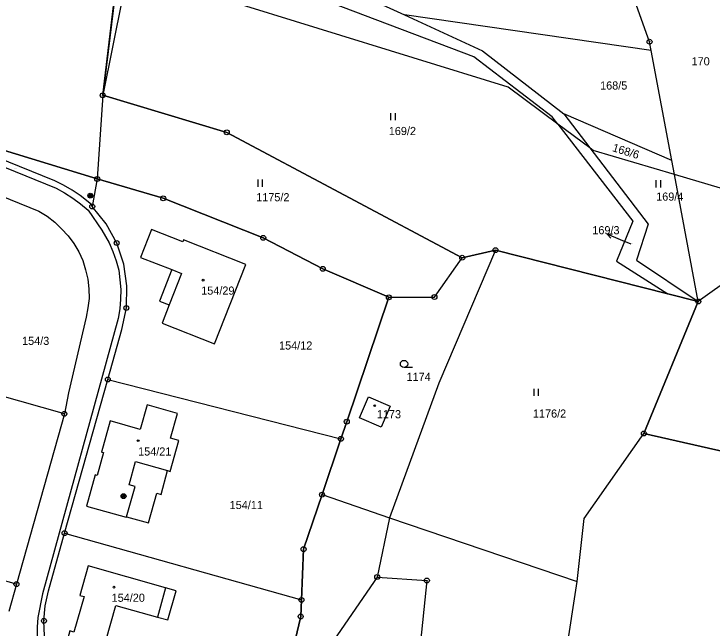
# Model space of a CAD drawing. Extents: x -737240 to -735272, y -1119606 to -1117878.
# Drawn here: x -736684.5 to -736538.4, y -1119343.1 to -1119214.7 of the extents above; entities that cross this region are included whole.
import ezdxf

# ---------------------------------------------------------------- set-up
doc = ezdxf.new("R2010")
doc.units = 0
for name, color, linetype in [('Level 1', 7, 'Continuous'), ('Level 13', 7, 'Continuous'), ('Level 16', 7, 'Continuous'), ('Level 18', 7, 'Continuous'), ('Level 19', 7, 'Continuous'), ('Level 25', 7, 'Continuous'), ('Level 4', 7, 'Continuous')]:
    doc.layers.add(name, color=color, linetype=linetype)

msp = doc.modelspace()

# ---------------------------------------------------------------- linework, layer by layer
at = {"layer": 'Level 1'}
for p, q in [((-736665.92, -1119231.67), (-736662.64, -1119204.74)), ((-736660.57, -1119205.38), (-736665.92, -1119231.67)), ((-736551.17, -1119222.28), (-736602.8, -1119214.86)), ((-736546.85, -1119245.3), (-736551.17, -1119222.28)), ((-736665.92, -1119231.67), (-736667.06, -1119249.16)), ((-736569.47, -1119235.51), (-736564, -1119242.68)), ((-736546.85, -1119245.3), (-736569.47, -1119235.51)), ((-736564, -1119242.68), (-736570.67, -1119237.72)), ((-736546.3, -1119248.23), (-736546.85, -1119245.3)), ((-736667.06, -1119249.16), (-736668.11, -1119254.91)), ((-736541.31, -1119274.79), (-736546.3, -1119248.23)), ((-736536.7, -1119251.07), (-736546.3, -1119248.23)), ((-736590.7, -1119265.63), (-736583.76, -1119264.06)), ((-736541.31, -1119274.79), (-736547.66, -1119273.19)), ((-736673.94, -1119298.28), (-736743.14, -1119278.79)), ((-736673.89, -1119323.23), (-736664.84, -1119291.08)), ((-736664.84, -1119291.08), (-736616.08, -1119303.51)), ((-736673.94, -1119298.28), (-736683.96, -1119333.89)), ((-736620.03, -1119315.17), (-736605.9, -1119319.98)), ((-736605.9, -1119319.98), (-736608.48, -1119332.39)), ((-736605.9, -1119319.98), (-736566.63, -1119333.35)), ((-736683.96, -1119333.89), (-736726.33, -1119321.96)), ((-736673.89, -1119323.23), (-736624.34, -1119337.18)), ((-736683.96, -1119333.89), (-736685.57, -1119339.6))]:
    msp.add_line(p, q, dxfattribs=at)
for points in [[(-736667.06, -1119249.16), (-736691.06, -1119241.83), (-736704.74, -1119235.5), (-736723.73, -1119226.81), (-736743.15, -1119221.74), (-736738.77, -1119203.51), (-736735.65, -1119190.52), (-736731.56, -1119173.9), (-736724.99, -1119172.93), (-736717.53, -1119171.82), (-736710.06, -1119170.71), (-736704.98, -1119169.96), (-736702.42, -1119170.42), (-736693.71, -1119172), (-736673.69, -1119175.61), (-736662.64, -1119204.74), (-736665.92, -1119231.67)], [(-736667.36, -1119176.68), (-736655.78, -1119192.66), (-736619.36, -1119207.27), (-736602.8, -1119214.86)], [(-736551.17, -1119222.28), (-736551.51, -1119220.47), (-736560.76, -1119194.73)], [(-736570.67, -1119237.72), (-736571.87, -1119236.16), (-736588.24, -1119223.64), (-736658.83, -1119196.84)], [(-736570.67, -1119237.72), (-736581.11, -1119229.95), (-736660.57, -1119205.38)], [(-736668.11, -1119254.91), (-736668.26, -1119254.47), (-736670.65, -1119252.61), (-736672.34, -1119251.49), (-736674.09, -1119250.44), (-736675.92, -1119249.53), (-736724.83, -1119229.75), (-736740.44, -1119225.23), (-736766.11, -1119219.16), (-736789.8, -1119214.25), (-736792.59, -1119213.62), (-736794.57, -1119213.03), (-736796.41, -1119212.17), (-736798.16, -1119211.14), (-736800.29, -1119209.7), (-736802.05, -1119208.36)], [(-736602.8, -1119214.86), (-736586.47, -1119222.35), (-736569.47, -1119235.51)], [(-736743.15, -1119221.74), (-736723.73, -1119226.81), (-736704.74, -1119235.5), (-736691.06, -1119241.83), (-736667.06, -1119249.16)], [(-736725.28, -1119230.97), (-736675.67, -1119251.11), (-736673.88, -1119252.07), (-736672.17, -1119253.15), (-736670.53, -1119254.37), (-736668.98, -1119255.66), (-736666.07, -1119259.85), (-736664.6, -1119262.5), (-736663.8, -1119264.36), (-736663.12, -1119266.27), (-736662.56, -1119268.23), (-736662.12, -1119272.27), (-736662.17, -1119274.3), (-736662.34, -1119276.33), (-736662.7, -1119278.32), (-736678.5, -1119335.91), (-736679.46, -1119340.86), (-736679.62, -1119342.87), (-736679.66, -1119344.9)], [(-736665.92, -1119231.67), (-736639.96, -1119239.42), (-736590.7, -1119265.63)], [(-736547.66, -1119273.19), (-736583.76, -1119264.06), (-736590.7, -1119265.63), (-736639.96, -1119239.42), (-736665.92, -1119231.67)], [(-736727.41, -1119236.65), (-736721.33, -1119238.79), (-736679.28, -1119255.92), (-736677.56, -1119256.95), (-736675.95, -1119258.17), (-736674.51, -1119259.56), (-736673.16, -1119261.07), (-736671.93, -1119262.67), (-736670.89, -1119264.4), (-736670.07, -1119266.22), (-736669.49, -1119268.16), (-736669.01, -1119270.12), (-736668.79, -1119272.11), (-736668.75, -1119274.14), (-736669.01, -1119276.12), (-736669.38, -1119278.07), (-736673.08, -1119293.85), (-736673.94, -1119298.28)], [(-736570.67, -1119237.72), (-736555.03, -1119257.98), (-736558.4, -1119266.33), (-736547.66, -1119273.19)], [(-736564, -1119242.68), (-736551.82, -1119258.62), (-736554.23, -1119266.17), (-736541.31, -1119274.79)], [(-736546.3, -1119248.23), (-736563.32, -1119243.18), (-736564, -1119242.68)], [(-736606.04, -1119273.9), (-736619.86, -1119267.96), (-736632.34, -1119261.47), (-736653.26, -1119253.2), (-736667.06, -1119249.16)], [(-736667.06, -1119249.16), (-736653.26, -1119253.2), (-736632.34, -1119261.47), (-736619.86, -1119267.96), (-736606.04, -1119273.9), (-736614.86, -1119299.91), (-736616.08, -1119303.51)], [(-736664.84, -1119291.08), (-736661.91, -1119280.67), (-736660.97, -1119276.14), (-736660.84, -1119271.52), (-736661.52, -1119266.95), (-736662.99, -1119262.56), (-736665.21, -1119258.51), (-736668.11, -1119254.91)], [(-736652.01, -1119275.5), (-736653.51, -1119279.28), (-736642.5, -1119283.65), (-736635.96, -1119267.07), (-736649.01, -1119261.87), (-736649.18, -1119262.29), (-736655.68, -1119259.72), (-736657.98, -1119265.55), (-736651.46, -1119268.12)], [(-736583.76, -1119264.06), (-736595.59, -1119291.89), (-736605.9, -1119319.98)], [(-736583.76, -1119264.06), (-736547.66, -1119273.19), (-736541.31, -1119274.79), (-736552.7, -1119302.39)], [(-736514.13, -1119266.89), (-736526.79, -1119264.4), (-736541.31, -1119274.79)], [(-736606.04, -1119273.9), (-736596.5, -1119273.85), (-736590.7, -1119265.63)], [(-736651.46, -1119268.12), (-736654.03, -1119274.69), (-736652.01, -1119275.5)], [(-736552.7, -1119302.39), (-736528.73, -1119307.83), (-736514.13, -1119266.89), (-736506.87, -1119269.54)], [(-736514.13, -1119266.89), (-736528.73, -1119307.83), (-736552.7, -1119302.39), (-736541.31, -1119274.79)], [(-736620.03, -1119315.17), (-736616.08, -1119303.51), (-736614.86, -1119299.91), (-736606.04, -1119273.9)], [(-736607.63, -1119301.03), (-736612.17, -1119299.1), (-736610.34, -1119294.74), (-736605.78, -1119296.68), (-736607.63, -1119301.03)], [(-736652.33, -1119310.15), (-736651.82, -1119310.3), (-736649.98, -1119303.84), (-736651.71, -1119303.34), (-736650.26, -1119298.23), (-736656.62, -1119296.42), (-736658.07, -1119301.52), (-736664.33, -1119299.74), (-736666.16, -1119306.26), (-736665.74, -1119306.37), (-736667.08, -1119311.17), (-736667.5, -1119311.05), (-736669.33, -1119317.54), (-736660.99, -1119319.86), (-736660.96, -1119319.78)], [(-736566.63, -1119333.35), (-736565.21, -1119320.17), (-736552.7, -1119302.39)], [(-736616.08, -1119303.51), (-736620.03, -1119315.17), (-736623.89, -1119326.56), (-736624.34, -1119337.18)], [(-736660.96, -1119319.78), (-736656.35, -1119321.09), (-736654.58, -1119314.89), (-736653.71, -1119315.14), (-736652.33, -1119310.15)], [(-736631.83, -1119443.36), (-736631.2, -1119439.41), (-736629.41, -1119428.11), (-736626.1, -1119402.13), (-736624.78, -1119391.75), (-736629.05, -1119368.06), (-736629.89, -1119363.38), (-736624.49, -1119340.65), (-736624.34, -1119337.18), (-736623.89, -1119326.56), (-736620.03, -1119315.17)], [(-736675.06, -1119355.1), (-736675.62, -1119353.87), (-736676.81, -1119350.93), (-736677.65, -1119347.86), (-736678.12, -1119344.72), (-736678.21, -1119341.54), (-736677.94, -1119338.4), (-736677.28, -1119335.26), (-736673.89, -1119323.23)], [(-736652.75, -1119334.65), (-736668.96, -1119330.07), (-736670.7, -1119336.24), (-736669.82, -1119336.48), (-736671.93, -1119343.89), (-736672.77, -1119343.67), (-736674.47, -1119349.8), (-736662.45, -1119353.14), (-736660.76, -1119347.02), (-736665.26, -1119345.76), (-736663.17, -1119338.35), (-736654.48, -1119340.76)], [(-736608.48, -1119332.39), (-736618.33, -1119346.74), (-736620.94, -1119359.13), (-736620.36, -1119374.23)], [(-736608.48, -1119332.39), (-736598.09, -1119333.13), (-736602.26, -1119373.59)], [(-736556.6, -1119455.53), (-736564.1, -1119433), (-736569.62, -1119411.99), (-736570.66, -1119398.36), (-736570.4, -1119373.52), (-736571.28, -1119363.31), (-736566.63, -1119333.35)], [(-736654.48, -1119340.76), (-736652.28, -1119341.36), (-736650.57, -1119335.27), (-736652.75, -1119334.65)], [(-736624.34, -1119337.18), (-736624.49, -1119340.65), (-736629.89, -1119363.38), (-736629.05, -1119368.06)]]:
    msp.add_lwpolyline(points, dxfattribs=at)
at = {"layer": 'Level 13'}
for points in [[(-736480.32, -1119178.48), (-736487.04, -1119219.97), (-736500.16, -1119254.99), (-736506.87, -1119269.54), (-736514.13, -1119266.89), (-736528.73, -1119307.83), (-736552.7, -1119302.39), (-736541.31, -1119274.79), (-736547.66, -1119273.19), (-736583.76, -1119264.06), (-736590.7, -1119265.63), (-736639.96, -1119239.42), (-736665.92, -1119231.67), (-736662.64, -1119204.74)], [(-736480.32, -1119178.48), (-736487.04, -1119219.97), (-736500.16, -1119254.99), (-736506.87, -1119269.54), (-736514.13, -1119266.89), (-736528.73, -1119307.83), (-736552.7, -1119302.39), (-736541.31, -1119274.79), (-736547.66, -1119273.19), (-736583.76, -1119264.06), (-736590.7, -1119265.63), (-736639.96, -1119239.42), (-736665.92, -1119231.67), (-736662.64, -1119204.74)], [(-736691.06, -1119241.83), (-736667.06, -1119249.16), (-736653.26, -1119253.2), (-736632.34, -1119261.47), (-736619.86, -1119267.96), (-736606.04, -1119273.9), (-736614.86, -1119299.91), (-736616.08, -1119303.51), (-736620.03, -1119315.17), (-736623.89, -1119326.56), (-736624.34, -1119337.18), (-736624.49, -1119340.65), (-736629.89, -1119363.38), (-736629.05, -1119368.06), (-736624.78, -1119391.75), (-736626.1, -1119402.13), (-736629.41, -1119428.11), (-736631.2, -1119439.41), (-736631.83, -1119443.36), (-736644.26, -1119449.01), (-736681.09, -1119435.63), (-736683, -1119434.94), (-736691.9, -1119431.7)], [(-736691.06, -1119241.83), (-736667.06, -1119249.16), (-736653.26, -1119253.2), (-736632.34, -1119261.47), (-736619.86, -1119267.96), (-736606.04, -1119273.9), (-736614.86, -1119299.91), (-736616.08, -1119303.51), (-736620.03, -1119315.17), (-736623.89, -1119326.56), (-736624.34, -1119337.18), (-736624.49, -1119340.65), (-736629.89, -1119363.38), (-736629.05, -1119368.06), (-736624.78, -1119391.75), (-736626.1, -1119402.13), (-736629.41, -1119428.11), (-736631.2, -1119439.41), (-736631.83, -1119443.36), (-736644.26, -1119449.01), (-736681.09, -1119435.63), (-736683, -1119434.94), (-736691.9, -1119431.7)]]:
    msp.add_lwpolyline(points, dxfattribs=at)
at = {"layer": 'Level 16'}
for points in [[(-736559.62, -1119261.563), (-736560.355, -1119260.721), (-736559.24, -1119260.638)], [(-736555.34, -1119262.78), (-736557.58, -1119261.86), (-736560.355, -1119260.721)]]:
    msp.add_lwpolyline(points, dxfattribs=at)
at = {"layer": 'Level 25'}
for p, q in [((-736605.707, -1119235.375), (-736605.707, -1119236.875)), ((-736604.685, -1119236.875), (-736604.685, -1119235.375)), ((-736633.487, -1119249.285), (-736633.487, -1119250.785)), ((-736632.465, -1119250.785), (-736632.465, -1119249.285)), ((-736550.187, -1119249.415), (-736550.187, -1119250.915)), ((-736549.165, -1119250.915), (-736549.165, -1119249.415)), ((-736601.098, -1119288.6), (-736602.88, -1119288.6)), ((-736575.737, -1119293.025), (-736575.737, -1119294.525)), ((-736574.715, -1119294.525), (-736574.715, -1119293.025))]:
    msp.add_line(p, q, dxfattribs=at)
for centre, major_axis, ratio in [((-736551.51, -1119220.47), (0.516, 0), 0.9848078), ((-736551.51, -1119220.47), (0.0375, 0), 0.9848078), ((-736665.92, -1119231.67), (0.516, 0), 0.9848078), ((-736665.92, -1119231.67), (0.0375, 0), 0.9848078), ((-736639.96, -1119239.42), (0.516, 0), 0.9848078), ((-736639.96, -1119239.42), (0.0375, 0), 0.9848078), ((-736667.06, -1119249.16), (0.516, 0), 0.9848078), ((-736667.06, -1119249.16), (0.0375, 0), 0.9848078), ((-736668.51, -1119252.66), (0.516, 0), 0.9848078), ((-736668.51, -1119252.66), (0.309, 0), 0.9848078), ((-736668.51, -1119252.66), (0.155, 0), 0.9848078), ((-736653.26, -1119253.2), (0.516, 0), 0.9848078), ((-736653.26, -1119253.2), (0.0375, 0), 0.9848078), ((-736668.11, -1119254.91), (0.516, 0), 0.9848078), ((-736668.11, -1119254.91), (0.0375, 0), 0.9848078), ((-736632.34, -1119261.47), (0.516, 0), 0.9848078), ((-736662.99, -1119262.56), (0.516, 0), 0.9848078), ((-736632.34, -1119261.47), (0.0375, 0), 0.9848078), ((-736662.99, -1119262.56), (0.0375, 0), 0.9848078), ((-736583.76, -1119264.06), (0.516, 0), 0.9848078), ((-736590.7, -1119265.63), (0.516, 0), 0.9848078), ((-736583.76, -1119264.06), (0.0375, 0), 0.9848078), ((-736590.7, -1119265.63), (0.0375, 0), 0.9848078), ((-736619.86, -1119267.96), (0.516, 0), 0.9848078), ((-736619.86, -1119267.96), (0.0375, 0), 0.9848078), ((-736644.92, -1119270.32), (0.18, 0), 0.9848078), ((-736606.04, -1119273.9), (0.516, 0), 0.9848078), ((-736606.04, -1119273.9), (0.0375, 0), 0.9848078), ((-736596.5, -1119273.85), (0.516, 0), 0.9848078), ((-736596.5, -1119273.85), (0.0375, 0), 0.9848078), ((-736541.31, -1119274.79), (0.516, 0), 0.9848078), ((-736541.31, -1119274.79), (0.0375, 0), 0.9848078), ((-736660.97, -1119276.14), (0.516, 0), 0.9848078), ((-736660.97, -1119276.14), (0.0375, 0), 0.9848078), ((-736602.88, -1119287.844), (0.764, 0), 0.9894236), ((-736664.84, -1119291.08), (0.516, 0), 0.9848078), ((-736664.84, -1119291.08), (0.0375, 0), 0.9848078), ((-736609.01, -1119296.57), (0.18, 0), 0.9848078), ((-736673.94, -1119298.28), (0.516, 0), 0.9848078), ((-736673.94, -1119298.28), (0.0375, 0), 0.9848078), ((-736614.86, -1119299.91), (0.516, 0), 0.9848078), ((-736614.86, -1119299.91), (0.0375, 0), 0.9848078), ((-736552.7, -1119302.39), (0.516, 0), 0.9848078), ((-736616.08, -1119303.51), (0.516, 0), 0.9848078), ((-736552.7, -1119302.39), (0.0375, 0), 0.9848078), ((-736658.5, -1119303.89), (0.18, 0), 0.9848078), ((-736616.08, -1119303.51), (0.0375, 0), 0.9848078), ((-736661.55, -1119315.47), (0.516, 0), 0.9848078), ((-736620.03, -1119315.17), (0.516, 0), 0.9848078), ((-736661.55, -1119315.47), (0.309, 0), 0.9848078), ((-736661.55, -1119315.47), (0.155, 0), 0.9848078), ((-736620.03, -1119315.17), (0.0375, 0), 0.9848078), ((-736673.89, -1119323.23), (0.516, 0), 0.9848078), ((-736673.89, -1119323.23), (0.0375, 0), 0.9848078), ((-736623.89, -1119326.56), (0.516, 0), 0.9848078), ((-736623.89, -1119326.56), (0.0375, 0), 0.9848078), ((-736608.48, -1119332.39), (0.516, 0), 0.9848078), ((-736608.48, -1119332.39), (0.0375, 0), 0.9848078), ((-736683.96, -1119333.89), (0.516, 0), 0.9848078), ((-736683.96, -1119333.89), (0.0375, 0), 0.9848078), ((-736598.09, -1119333.13), (0.516, 0), 0.9848078), ((-736598.09, -1119333.13), (0.0375, 0), 0.9848078), ((-736663.56, -1119334.51), (0.18, 0), 0.9848078), ((-736624.34, -1119337.18), (0.516, 0), 0.9848078), ((-736624.34, -1119337.18), (0.0375, 0), 0.9848078), ((-736678.21, -1119341.54), (0.516, 0), 0.9848078), ((-736624.49, -1119340.65), (0.516, 0), 0.9848078), ((-736624.49, -1119340.65), (0.0375, 0), 0.9848078), ((-736678.21, -1119341.54), (0.0375, 0), 0.9848078)]:
    msp.add_ellipse(centre, major_axis=major_axis, ratio=ratio, dxfattribs=at)
at = {"layer": 'Level 4'}
msp.add_line((-736652.75, -1119334.65), (-736654.48, -1119340.76), dxfattribs=at)
for points in [[(-736651.46, -1119268.12), (-736649.4, -1119268.92), (-736652.01, -1119275.5)], [(-736660.96, -1119319.78), (-736659.16, -1119313.43), (-736660.4, -1119313.08), (-736659.03, -1119308.21), (-736652.33, -1119310.15)]]:
    msp.add_lwpolyline(points, dxfattribs=at)

# ---------------------------------------------------------------- texts
at = {"layer": 'Level 16'}
msp.add_text('169/3', height=1.7, dxfattribs=at).set_placement((-736563.485, -1119260.72))
at = {"layer": 'Level 18'}
for s, height, p in [('170', 1.7, (-736542.715, -1119225.41)), ('168/5', 1.7, (-736561.855, -1119230.47)), ('169/2', 1.7, (-736606.065, -1119239.98)), ('154/24', 0.1, (-736684.34, -1119247.09)), ('1175/2', 1.7, (-736633.8, -1119253.83)), ('169/4', 1.7, (-736550.125, -1119253.7)), ('169/3', 0.1, (-736555.215, -1119262.78)), ('154/3', 1.7, (-736682.785, -1119283.86)), ('154/12', 1.7, (-736629.02, -1119284.83)), ('1174', 1.7, (-736602.35, -1119291.38)), ('1176/2', 1.7, (-736575.91, -1119299.06)), ('154/11', 1.7, (-736639.36, -1119318.18))]:
    msp.add_text(s, height=height, dxfattribs=at).set_placement(p)
msp.add_text('168/6', height=1.7, rotation=342.60849, dxfattribs=at).set_placement((-736559.422, -1119243.315))
at = {"layer": 'Level 19'}
for s, p in [('154/29', (-736645.305, -1119273.35)), ('1173', (-736608.565, -1119299.2)), ('154/21', (-736658.505, -1119306.99)), ('154/20', (-736664.045, -1119337.57))]:
    msp.add_text(s, height=1.7, dxfattribs=at).set_placement(p)

doc.saveas('drawing.dxf')
